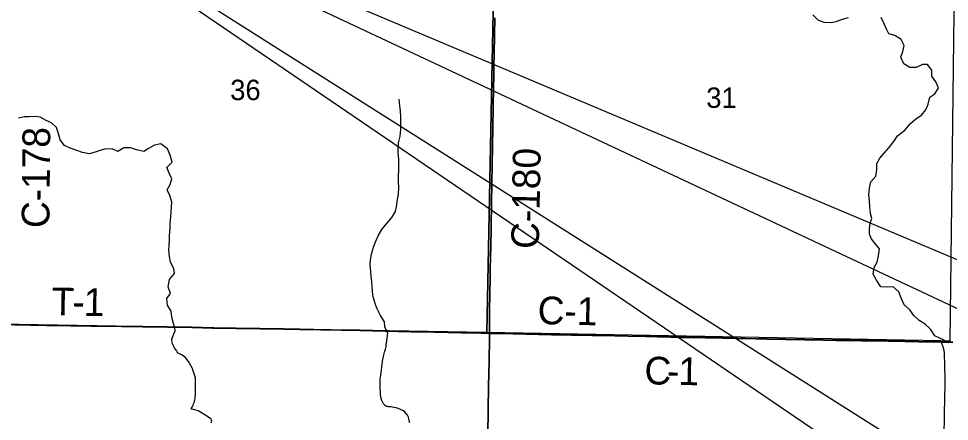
# Model space of a CAD drawing. Extents: x 0 to 34, y 0 to 22.
# Drawn here: x 5.686 to 7.593, y 16.256 to 17.081 of the extents above; entities that cross this region are included whole.
import ezdxf

# ---------------------------------------------------------------- set-up
doc = ezdxf.new("R2010")
doc.units = 0
for name, color, linetype in [('GM_X_County_Road', 7, 'Continuous'), ('GM_X_County_Road_Text', 7, 'Continuous'), ('GM_X_County_Text', 7, 'Continuous'), ('GM_X_Minor_River', 7, 'Continuous'), ('GM_X_Section', 7, 'Continuous'), ('GM_X_Section_Text', 7, 'Continuous'), ('GM_X_Township_Road', 7, 'Continuous'), ('GM_X_Township_Road_Text', 7, 'Continuous'), ('SH_Cut_Line', 7, 'Continuous'), ('TX_P_1', 7, 'Continuous')]:
    doc.layers.add(name, color=color, linetype=linetype)

msp = doc.modelspace()

# ---------------------------------------------------------------- linework, layer by layer
at = {"layer": 'GM_X_County_Road'}
for points in [[(6.651, 16.4362), (6.6508, 16.4516), (6.6508, 16.4566), (6.6509, 16.4628), (6.651, 16.469), (6.6511, 16.4727), (6.6511, 16.4777), (6.6512, 16.4845), (6.6514, 16.4914), (6.6517, 16.5081), (6.6517, 16.5125), (6.6518, 16.5168), (6.6519, 16.5218), (6.652, 16.5261), (6.6521, 16.5305), (6.6522, 16.5354), (6.6522, 16.5404), (6.6523, 16.5497), (6.6524, 16.5559), (6.6525, 16.5603), (6.6525, 16.5653), (6.6526, 16.5727), (6.6527, 16.5752), (6.6529, 16.5839), (6.653, 16.5919), (6.6535, 16.6156), (6.6542, 16.6473), (6.6544, 16.6584), (6.6547, 16.6721), (6.6549, 16.6852), (6.6551, 16.697), (6.6553, 16.7106), (6.6556, 16.733), (6.6557, 16.7405), (6.6559, 16.7504), (6.6565, 16.7753), (6.6566, 16.784), (6.6568, 16.7939), (6.657, 16.8063), (6.6572, 16.8188), (6.6574, 16.8312), (6.6577, 16.8461), (6.6578, 16.8579), (6.658, 16.8716), (6.6583, 16.8859), (6.6586, 16.8989), (6.6589, 16.9138), (6.6591, 16.9263), (6.6593, 16.9362), (6.6595, 16.9468), (6.6596, 16.9555), (6.6598, 16.9642), (6.66, 16.9772), (6.6602, 16.9915), (6.6604, 17.0002), (6.6606, 17.0127), (6.6608, 17.0214), (6.6611, 17.0332), (6.6614, 17.0468), (6.6616, 17.0593), (6.6618, 17.0704), (6.6621, 17.0822)], [(6.651, 16.4362), (6.6991, 16.4351), (6.7775, 16.4335), (6.8191, 16.4328), (6.8608, 16.432), (6.8775, 16.4318), (6.9074, 16.4311), (6.9353, 16.4303), (6.9714, 16.4296), (6.995, 16.429), (7.0217, 16.4285), (7.0416, 16.4279), (7.0572, 16.4276), (7.128, 16.4263), (7.1597, 16.4256), (7.1753, 16.4254), (7.2188, 16.4242), (7.3344, 16.4222), (7.3605, 16.4219), (7.3704, 16.4218), (7.3859, 16.4218), (7.3984, 16.4216), (7.4127, 16.4212), (7.4319, 16.4209), (7.4474, 16.4206), (7.4679, 16.4201), (7.5021, 16.4195), (7.5301, 16.4189), (7.5562, 16.4186), (7.5766, 16.4183)], [(7.5766, 16.4183), (7.5817, 16.4182), (7.6, 16.4178)]]:
    msp.add_lwpolyline(points, dxfattribs=at)
at = {"layer": 'GM_X_County_Text'}
for points in [[(5.6775, 16.4542), (5.7427, 16.4528), (5.7924, 16.452), (5.8347, 16.4514), (5.8975, 16.4505), (5.9404, 16.45), (6.0417, 16.4486), (6.0833, 16.4477), (6.2286, 16.4452), (6.2622, 16.4447), (6.3478, 16.4431), (6.3852, 16.4426), (6.4896, 16.4402), (6.5381, 16.4393), (6.5934, 16.4382), (6.6338, 16.4373), (6.639, 16.4371), (6.6508, 16.4368), (6.6506, 16.4522), (6.6506, 16.4571), (6.6507, 16.4633), (6.6508, 16.4696), (6.6508, 16.4733), (6.6509, 16.4783), (6.651, 16.4851), (6.6511, 16.4919), (6.6514, 16.5087), (6.6515, 16.513), (6.6516, 16.5174), (6.6517, 16.5224), (6.6518, 16.5267), (6.6518, 16.531), (6.6519, 16.536), (6.6519, 16.541), (6.6521, 16.5503), (6.6521, 16.5565), (6.6522, 16.5608), (6.6523, 16.5658), (6.6524, 16.5733), (6.6524, 16.5757), (6.6526, 16.5844), (6.6527, 16.5925), (6.6533, 16.6161), (6.6539, 16.6478), (6.6541, 16.659), (6.6544, 16.6727), (6.6547, 16.6857), (6.6549, 16.6975), (6.6551, 16.7112), (6.6554, 16.7336), (6.6555, 16.741), (6.6557, 16.751), (6.6562, 16.7758), (6.6564, 16.7845), (6.6565, 16.7944), (6.6567, 16.8069), (6.657, 16.8193), (6.6572, 16.8317), (6.6574, 16.8467), (6.6576, 16.8585), (6.6578, 16.8721), (6.658, 16.8864), (6.6583, 16.8995), (6.6586, 16.9144), (6.6589, 16.9268), (6.6591, 16.9368), (6.6593, 16.9473), (6.6594, 16.956), (6.6596, 16.9647), (6.6598, 16.9778), (6.66, 16.9921), (6.6601, 17.0008), (6.6604, 17.0132), (6.6606, 17.0219), (6.6608, 17.0337), (6.6611, 17.0474), (6.6614, 17.0598), (6.6616, 17.071), (6.6618, 17.0828)], [(6.6618, 17.0828), (6.6616, 17.071), (6.6614, 17.0598), (6.6611, 17.0474), (6.6608, 17.0337), (6.6606, 17.0219), (6.6604, 17.0132), (6.6601, 17.0008), (6.66, 16.9921), (6.6598, 16.9778), (6.6596, 16.9647), (6.6594, 16.956), (6.6593, 16.9473), (6.6591, 16.9368), (6.6589, 16.9268), (6.6586, 16.9144), (6.6583, 16.8995), (6.658, 16.8864), (6.6578, 16.8721), (6.6576, 16.8585), (6.6574, 16.8467), (6.6572, 16.8317), (6.657, 16.8193), (6.6567, 16.8069), (6.6565, 16.7944), (6.6564, 16.7845), (6.6562, 16.7758), (6.6557, 16.751), (6.6555, 16.741), (6.6554, 16.7336), (6.6551, 16.7112), (6.6549, 16.6975), (6.6547, 16.6857), (6.6544, 16.6727), (6.6541, 16.659), (6.6539, 16.6478), (6.6533, 16.6161), (6.6527, 16.5925), (6.6526, 16.5844), (6.6524, 16.5757), (6.6524, 16.5733), (6.6523, 16.5658), (6.6522, 16.5608), (6.6521, 16.5565), (6.6521, 16.5503), (6.6519, 16.541), (6.6519, 16.536), (6.6518, 16.531), (6.6518, 16.5267), (6.6517, 16.5224), (6.6516, 16.5174), (6.6515, 16.513), (6.6514, 16.5087), (6.6511, 16.4919), (6.651, 16.4851), (6.6509, 16.4783), (6.6508, 16.4733), (6.6508, 16.4696), (6.6507, 16.4633), (6.6506, 16.4571), (6.6506, 16.4522), (6.6508, 16.4368), (6.6989, 16.4357), (6.7772, 16.4341), (6.8189, 16.4333), (6.8605, 16.4325), (6.8773, 16.4323), (6.9072, 16.4316), (6.9351, 16.4308), (6.9712, 16.4301), (6.9948, 16.4295), (7.0215, 16.4291), (7.0414, 16.4285), (7.0569, 16.4281), (7.1278, 16.4268), (7.1595, 16.4262), (7.175, 16.426), (7.2185, 16.4248), (7.3341, 16.4228), (7.3602, 16.4225), (7.3702, 16.4224), (7.3857, 16.4224), (7.3981, 16.4221), (7.4124, 16.4218), (7.4317, 16.4215), (7.4472, 16.4211), (7.4677, 16.4206), (7.5019, 16.42), (7.5299, 16.4194), (7.556, 16.4192), (7.5764, 16.4188), (7.5815, 16.4187), (7.5998, 16.4183)], [(6.6468, 16.2212), (6.6478, 16.2647), (6.6481, 16.2802), (6.6488, 16.3275), (6.6499, 16.3797), (6.6506, 16.4257), (6.6508, 16.4368), (6.639, 16.4371), (6.6338, 16.4373), (6.5934, 16.4382), (6.5381, 16.4393), (6.4896, 16.4402), (6.3852, 16.4426), (6.3478, 16.4431), (6.2622, 16.4447), (6.2286, 16.4452), (6.0833, 16.4477), (6.0417, 16.4486), (5.9404, 16.45), (5.8975, 16.4505), (5.8347, 16.4514), (5.7924, 16.452), (5.7427, 16.4528), (5.6775, 16.4542)], [(7.5998, 16.4183), (7.5815, 16.4187), (7.5764, 16.4188), (7.556, 16.4192), (7.5299, 16.4194), (7.5019, 16.42), (7.4677, 16.4206), (7.4472, 16.4211), (7.4317, 16.4215), (7.4124, 16.4218), (7.3981, 16.4221), (7.3857, 16.4224), (7.3702, 16.4224), (7.3602, 16.4225), (7.3341, 16.4228), (7.2185, 16.4248), (7.175, 16.426), (7.1595, 16.4262), (7.1278, 16.4268), (7.0569, 16.4281), (7.0414, 16.4285), (7.0215, 16.4291), (6.9948, 16.4295), (6.9712, 16.4301), (6.9351, 16.4308), (6.9072, 16.4316), (6.8773, 16.4323), (6.8605, 16.4325), (6.8189, 16.4333), (6.7772, 16.4341), (6.6989, 16.4357), (6.6508, 16.4368), (6.6506, 16.4257), (6.6499, 16.3797), (6.6488, 16.3275), (6.6481, 16.2802), (6.6478, 16.2647), (6.6468, 16.2212)]]:
    msp.add_lwpolyline(points, dxfattribs=at)
at = {"layer": 'GM_X_Minor_River'}
for points in [[(7.3856, 17.0828), (7.373, 17.0797), (7.3604, 17.075), (7.3509, 17.0729), (7.3365, 17.0735), (7.3241, 17.0783), (7.3133, 17.0892)], [(7.5919, 16.4166), (7.5747, 16.426), (7.563, 16.4315), (7.5538, 16.4446), (7.5434, 16.4554), (7.5306, 16.4625), (7.5198, 16.473), (7.5117, 16.4845), (7.5001, 16.4946), (7.4947, 16.5068), (7.4889, 16.5214), (7.4774, 16.5315), (7.4644, 16.531), (7.4523, 16.5316), (7.4431, 16.545), (7.4365, 16.5577), (7.4387, 16.5709), (7.445, 16.5825), (7.4475, 16.5954), (7.4497, 16.6094), (7.44, 16.6209), (7.4326, 16.6306), (7.4294, 16.6401), (7.4288, 16.6507), (7.4302, 16.6621), (7.4338, 16.6719), (7.4313, 16.6818), (7.4297, 16.6955), (7.4288, 16.708), (7.4275, 16.7206), (7.4293, 16.7338), (7.4315, 16.747), (7.4423, 16.7586), (7.4441, 16.7722), (7.4443, 16.7847), (7.4502, 16.7952), (7.4591, 16.8053), (7.4688, 16.8165), (7.4786, 16.8292), (7.4867, 16.8412), (7.5014, 16.8526), (7.513, 16.8664), (7.5242, 16.8761), (7.5353, 16.8835), (7.5443, 16.8943), (7.5494, 16.9063), (7.5527, 16.9203), (7.5631, 16.9269), (7.5705, 16.9393), (7.5651, 16.9519), (7.5566, 16.9634), (7.5568, 16.976), (7.5476, 16.9871), (7.5377, 16.9873), (7.5243, 16.9815), (7.5114, 16.981), (7.4991, 16.9885), (7.4933, 17.0022), (7.4973, 17.0143), (7.5002, 17.026), (7.4936, 17.0386), (7.4809, 17.0468), (7.4688, 17.0501), (7.4637, 17.0597), (7.4593, 17.0704), (7.4531, 17.0838)], [(6.4425, 16.436), (6.4364, 16.4495), (6.4359, 16.46), (6.4278, 16.473), (6.4201, 16.488), (6.4169, 16.4975), (6.4126, 16.5113), (6.4113, 16.5215), (6.4103, 16.5329), (6.4098, 16.5428), (6.4084, 16.5531), (6.4075, 16.5637), (6.4066, 16.5766), (6.4072, 16.5868), (6.4101, 16.6016), (6.4138, 16.6148), (6.4178, 16.6249), (6.4229, 16.6362), (6.4304, 16.649), (6.4393, 16.6602), (6.4506, 16.6736), (6.458, 16.686), (6.4601, 16.6958), (6.4627, 16.7105), (6.4644, 16.7208), (6.4654, 16.7359), (6.4645, 16.7469), (6.4644, 16.7598), (6.465, 16.7704), (6.4652, 16.7837), (6.4654, 16.7935), (6.4638, 16.8069), (6.4636, 16.8167), (6.4642, 16.8266), (6.4678, 16.8405), (6.4692, 16.8538), (6.4695, 16.8663), (6.4693, 16.8792), (6.4688, 16.8921), (6.4675, 16.9027), (6.4659, 16.9164)], [(6.0074, 16.4435), (6, 16.4692), (5.9987, 16.4814), (5.9917, 16.4941), (5.9901, 16.5074), (5.9975, 16.5178), (5.9924, 16.5316), (5.9958, 16.5463), (6.0058, 16.5586), (6.0045, 16.5685), (5.9976, 16.5827), (5.9955, 16.5937), (5.9943, 16.6067), (5.9948, 16.6165), (5.9954, 16.6264), (5.9956, 16.6377), (5.997, 16.6506), (5.9968, 16.6605), (5.9982, 16.6756), (5.9988, 16.6854), (6, 16.7059), (5.9964, 16.7189), (5.9906, 16.7307), (5.9965, 16.7416), (6.0001, 16.7529), (5.9958, 16.7629), (5.99, 16.7763), (6.0012, 16.7874), (5.9965, 16.8015), (5.9911, 16.8145), (5.978, 16.825), (5.9647, 16.8219), (5.9524, 16.8149), (5.9428, 16.8087), (5.9281, 16.8127), (5.9157, 16.8168), (5.902, 16.8163), (5.8897, 16.8089), (5.8777, 16.8145), (5.8629, 16.8136), (5.853, 16.8108), (5.8434, 16.8076), (5.8309, 16.8044), (5.8176, 16.8069), (5.8056, 16.8109), (5.792, 16.8161), (5.7804, 16.8213), (5.7715, 16.8332), (5.7672, 16.8477), (5.764, 16.858), (5.7536, 16.8681), (5.7431, 16.8725), (5.7303, 16.8795), (5.7205, 16.8809), (5.7079, 16.88), (5.6981, 16.8798), (5.6859, 16.877)], [(6.0808, 16.2527), (6.082, 16.256), (6.0816, 16.258), (6.0806, 16.261), (6.078, 16.2626), (6.075, 16.2642), (6.0664, 16.2697), (6.0623, 16.2728), (6.054, 16.2772), (6.0453, 16.2801), (6.0404, 16.2806), (6.0405, 16.2829), (6.0417, 16.2851), (6.0437, 16.2892), (6.0445, 16.2915), (6.0453, 16.2934), (6.0465, 16.296), (6.0469, 16.2979), (6.0473, 16.3002), (6.0478, 16.3028), (6.0482, 16.3058), (6.0487, 16.3093), (6.0488, 16.3134), (6.0485, 16.3188), (6.0487, 16.3244), (6.0484, 16.3298), (6.0489, 16.3336), (6.049, 16.3381), (6.0487, 16.3412), (6.0484, 16.345), (6.0445, 16.3576), (6.0431, 16.361), (6.0424, 16.3641), (6.0413, 16.3668), (6.0398, 16.3687), (6.0384, 16.3718), (6.0373, 16.3737), (6.0355, 16.3764), (6.0322, 16.3811), (6.0274, 16.3876), (6.0199, 16.392), (6.0158, 16.3944), (6.0135, 16.3955), (6.0109, 16.3986), (6.0095, 16.4013), (6.0073, 16.4044), (6.0051, 16.4071), (6.004, 16.4091), (6.0029, 16.4121), (6.0018, 16.4148), (6.0011, 16.4186), (6.0005, 16.4217), (6.0005, 16.424), (6.0006, 16.4266), (6.0077, 16.4433)], [(6.4874, 16.2525), (6.4863, 16.257), (6.4853, 16.2616), (6.4846, 16.2643), (6.4828, 16.2685), (6.4765, 16.2759), (6.4735, 16.2779), (6.4709, 16.2791), (6.469, 16.2799), (6.4596, 16.2835), (6.4551, 16.2844), (6.4494, 16.2853), (6.4464, 16.2857), (6.4437, 16.2858), (6.4418, 16.2862), (6.4399, 16.2866), (6.4381, 16.2874), (6.4355, 16.2898), (6.4336, 16.2921), (6.4322, 16.2944), (6.43, 16.2987), (6.4289, 16.3025), (6.4283, 16.3063), (6.4276, 16.3112), (6.4274, 16.3162), (6.4271, 16.3215), (6.4268, 16.3268), (6.4266, 16.3314), (6.4267, 16.336), (6.4272, 16.3401), (6.4272, 16.3435), (6.4277, 16.3466), (6.4285, 16.3507), (6.429, 16.3556), (6.4296, 16.3613), (6.4301, 16.367), (6.431, 16.3727), (6.4319, 16.3795), (6.4328, 16.3856), (6.4345, 16.392), (6.4361, 16.398), (6.4378, 16.4037), (6.439, 16.409), (6.4395, 16.4139), (6.4399, 16.4158), (6.4424, 16.436)]]:
    msp.add_lwpolyline(points, dxfattribs=at)
at = {"layer": 'GM_X_Section'}
for points in [[(5.6551, 17.4555), (6.6654, 17.4415), (6.6455, 16.4378), (5.6459, 16.4551)], [(6.6654, 17.4415), (7.606, 17.4298), (7.5935, 16.4205), (7.5749, 16.4209), (6.6455, 16.4378)]]:
    msp.add_lwpolyline(points, close=True, dxfattribs=at)
at = {"layer": 'GM_X_Township_Road'}
for points in [[(5.6492, 16.4543), (5.6777, 16.4536), (5.743, 16.4523), (5.7927, 16.4515), (5.8349, 16.4509), (5.8977, 16.45), (5.9406, 16.4494), (6.0419, 16.448), (6.0836, 16.4472), (6.2288, 16.4446), (6.2624, 16.4442), (6.348, 16.4426), (6.3854, 16.4421), (6.4898, 16.4397), (6.5383, 16.4388), (6.5936, 16.4376), (6.634, 16.4368), (6.6392, 16.4366), (6.651, 16.4362)], [(6.647, 16.2206), (6.648, 16.2642), (6.6483, 16.2797), (6.649, 16.3269), (6.6501, 16.3792), (6.6508, 16.4252), (6.651, 16.4362)], [(6.651, 16.4362), (6.6991, 16.4351), (6.7775, 16.4335), (6.8191, 16.4328), (6.8608, 16.432), (6.8775, 16.4318), (6.9074, 16.4311), (6.9353, 16.4303), (6.9714, 16.4296), (6.995, 16.429), (7.0217, 16.4285), (7.0416, 16.4279), (7.0572, 16.4276), (7.128, 16.4263), (7.1597, 16.4256), (7.1753, 16.4254), (7.2188, 16.4242), (7.3344, 16.4222), (7.3605, 16.4219), (7.3704, 16.4218), (7.3859, 16.4218), (7.3984, 16.4216), (7.4127, 16.4212), (7.4319, 16.4209), (7.4474, 16.4206), (7.4679, 16.4201), (7.5021, 16.4195), (7.5301, 16.4189), (7.5562, 16.4186), (7.5766, 16.4183)], [(7.5856, 16.1081), (7.5835, 16.1126), (7.5825, 16.116), (7.582, 16.1194), (7.5818, 16.1226), (7.5815, 16.1346), (7.5814, 16.1591), (7.5816, 16.1896), (7.5829, 16.2666), (7.5836, 16.3082), (7.5838, 16.3274), (7.5838, 16.3479), (7.5836, 16.3641), (7.5835, 16.3746), (7.583, 16.3907), (7.5826, 16.3963), (7.5819, 16.4012), (7.5808, 16.4061), (7.5794, 16.4108), (7.5789, 16.412), (7.5766, 16.4183)], [(7.5766, 16.4183), (7.5817, 16.4182), (7.6, 16.4178)]]:
    msp.add_lwpolyline(points, dxfattribs=at)
at = {"layer": 'SH_Cut_Line'}
for points in [[(7.5998, 16.4183), (7.5815, 16.4187), (7.5764, 16.4188), (7.556, 16.4192), (7.5299, 16.4194), (7.5019, 16.42), (7.4677, 16.4206), (7.4472, 16.4211), (7.4317, 16.4215), (7.4124, 16.4218), (7.3981, 16.4221), (7.3857, 16.4224), (7.3702, 16.4224), (7.3602, 16.4225), (7.3341, 16.4228), (7.2185, 16.4248), (7.175, 16.426), (7.1595, 16.4262), (7.1278, 16.4268), (7.0569, 16.4281), (7.0414, 16.4285), (7.0215, 16.4291), (6.9948, 16.4295), (6.9712, 16.4301), (6.9351, 16.4308), (6.9072, 16.4316), (6.8773, 16.4323), (6.8605, 16.4325), (6.8189, 16.4333), (6.7772, 16.4341), (6.6989, 16.4357), (6.6508, 16.4368), (6.639, 16.4371), (6.6338, 16.4373), (6.5934, 16.4382), (6.5381, 16.4393), (6.4896, 16.4402), (6.3852, 16.4426), (6.3478, 16.4431), (6.2622, 16.4447), (6.2286, 16.4452), (6.0833, 16.4477), (6.0417, 16.4486), (5.9404, 16.45), (5.8975, 16.4505), (5.8347, 16.4514), (5.7924, 16.452), (5.7427, 16.4528), (5.6775, 16.4542)], [(5.6775, 16.4542), (5.7427, 16.4528), (5.7924, 16.452), (5.8347, 16.4514), (5.8975, 16.4505), (5.9404, 16.45), (6.0417, 16.4486), (6.0833, 16.4477), (6.2286, 16.4452), (6.2622, 16.4447), (6.3478, 16.4431), (6.3852, 16.4426), (6.4896, 16.4402), (6.5381, 16.4393), (6.5934, 16.4382), (6.6338, 16.4373), (6.639, 16.4371), (6.6508, 16.4368), (6.6989, 16.4357), (6.7772, 16.4341), (6.8189, 16.4333), (6.8605, 16.4325), (6.8773, 16.4323), (6.9072, 16.4316), (6.9351, 16.4308), (6.9712, 16.4301), (6.9948, 16.4295), (7.0215, 16.4291), (7.0414, 16.4285), (7.0569, 16.4281), (7.1278, 16.4268), (7.1595, 16.4262), (7.175, 16.426), (7.2185, 16.4248), (7.3341, 16.4228), (7.3602, 16.4225), (7.3702, 16.4224), (7.3857, 16.4224), (7.3981, 16.4221), (7.4124, 16.4218), (7.4317, 16.4215), (7.4472, 16.4211), (7.4677, 16.4206), (7.5019, 16.42), (7.5299, 16.4194), (7.556, 16.4192), (7.5764, 16.4188), (7.5815, 16.4187), (7.5998, 16.4183)]]:
    msp.add_lwpolyline(points, dxfattribs=at)
at = {"layer": 'TX_P_1'}
for points in [[(9.2734, 14.9035), (5.5187, 17.4627), (9.2734, 15.0836)], [(9.2734, 15.8853), (5.5318, 17.4627), (9.2734, 15.7052)]]:
    msp.add_lwpolyline(points, close=True, dxfattribs=at)

# ---------------------------------------------------------------- texts
at = {"layer": 'GM_X_County_Road_Text'}
for s, height, rotation, p in [('C-178', 0.05682, 89.4608, (5.7494, 16.6519)), ('C-180', 0.05682, 88.8983, (6.7519, 16.6089)), ('C-1', 0.05682, 358.7779, (6.749, 16.4553)), ('C', 0.0568, 358.7908, (6.9677, 16.332)), ('1', 0.0568, 358.8626, (7.0372, 16.3306)), ('-', 0.0568, 358.8513, (7.0141, 16.3311))]:
    msp.add_text(s, height=height, rotation=rotation, dxfattribs=at).set_placement(p)
at = {"layer": 'GM_X_Section_Text'}
for s, p in [('36', (6.1198, 16.9143)), ('31', (7.0948, 16.8984))]:
    msp.add_text(s, height=0.04186, rotation=0, dxfattribs=at).set_placement(p)
at = {"layer": 'GM_X_Township_Road_Text'}
for s, rotation, p in [('T', 358.936, (5.7538, 16.4735)), ('1', 358.9542, (5.8194, 16.4722)), ('-', 358.9441, (5.7963, 16.4727))]:
    msp.add_text(s, height=0.0568, rotation=rotation, dxfattribs=at).set_placement(p)

doc.saveas('drawing.dxf')
